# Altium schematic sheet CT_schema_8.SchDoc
size 391 x 238 mm
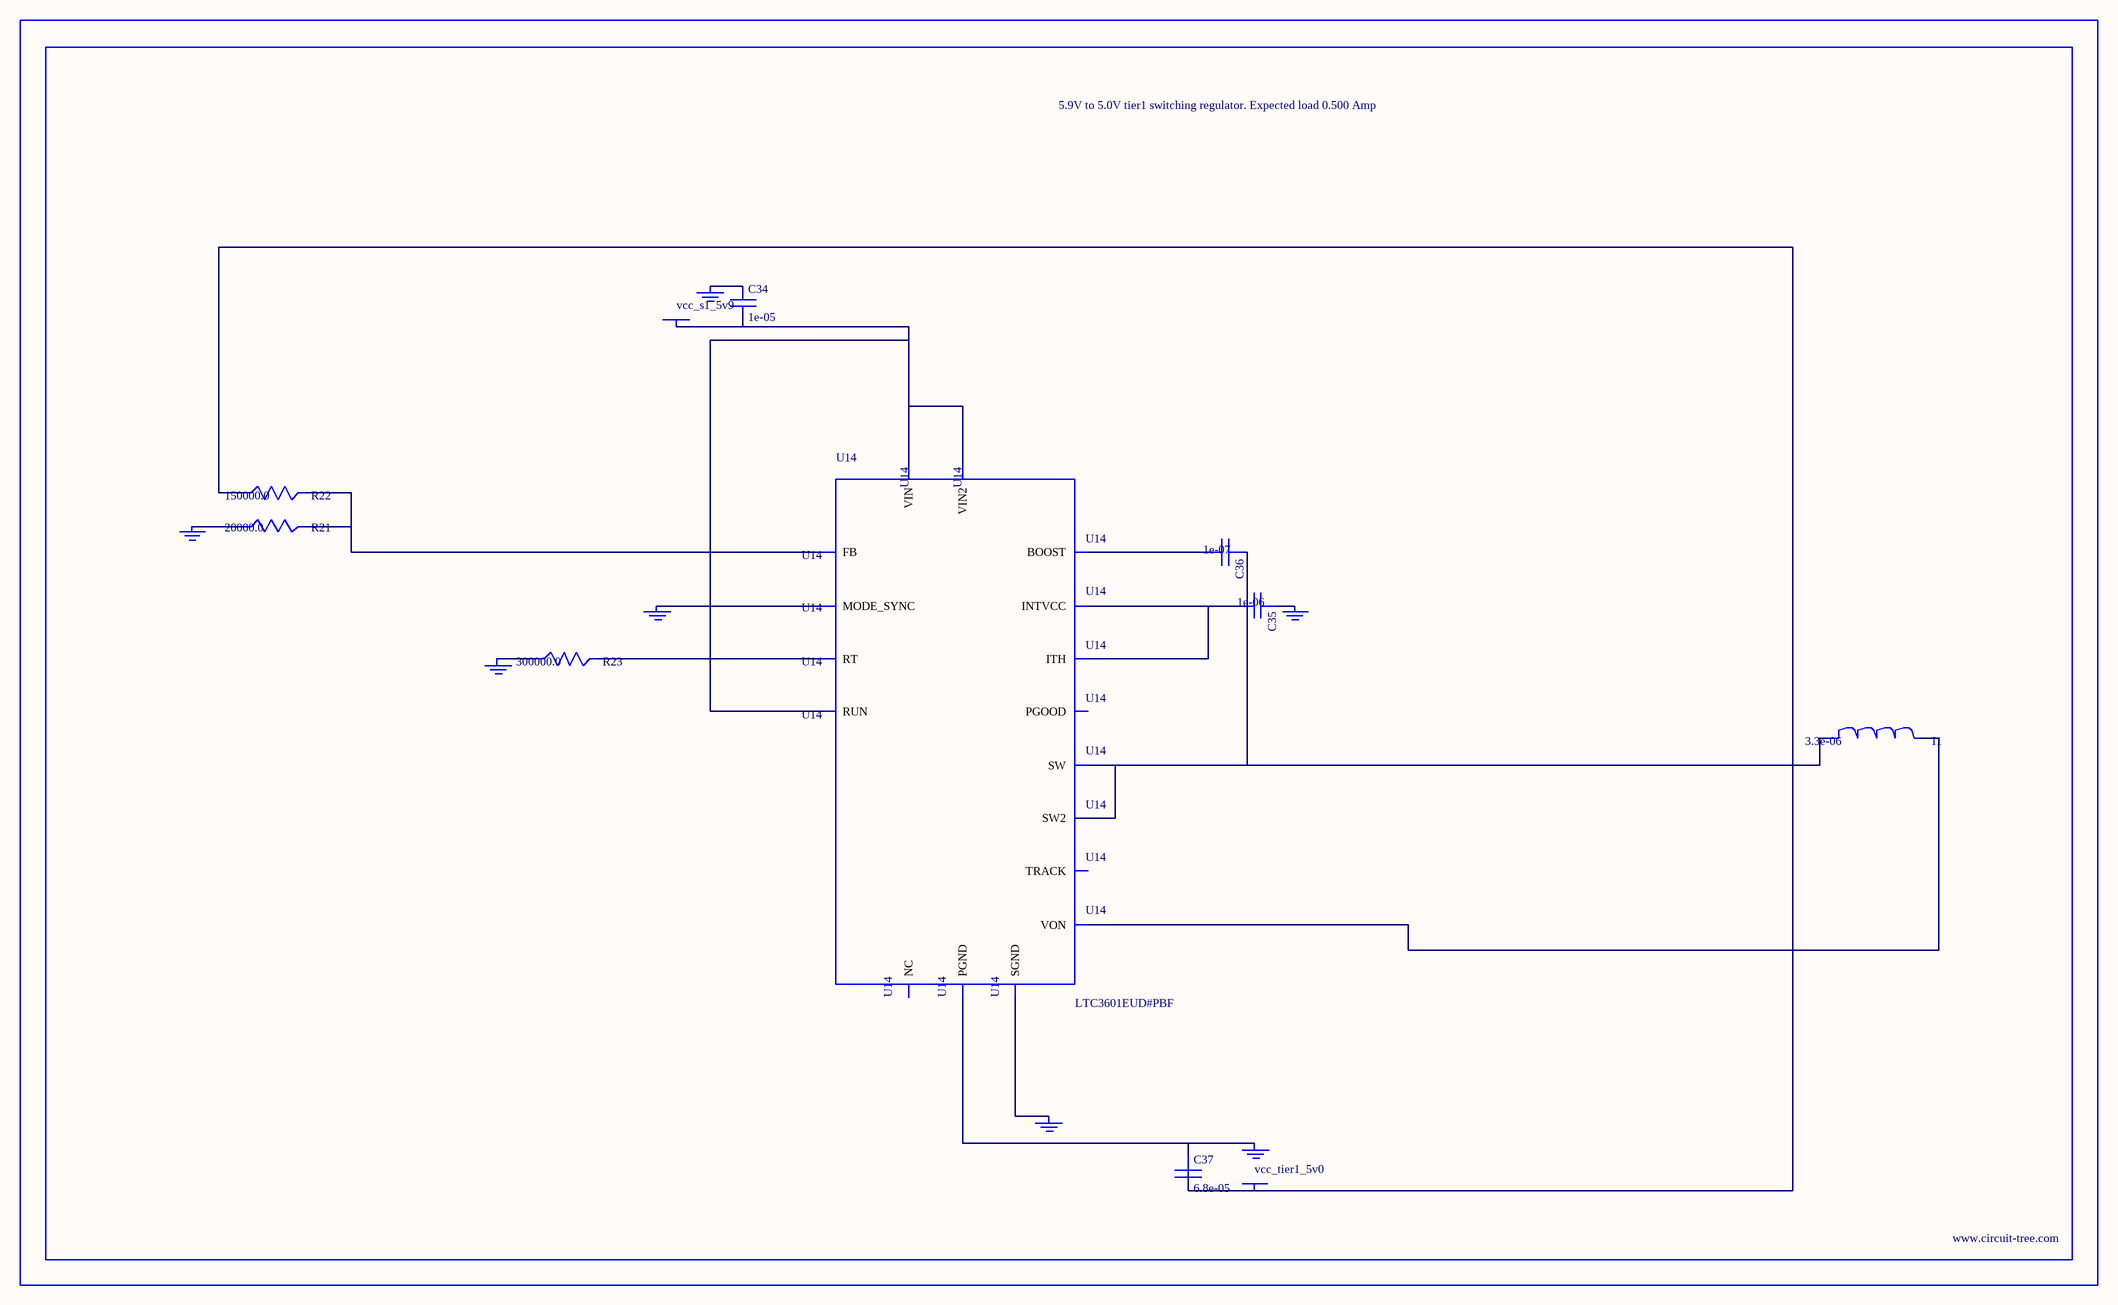
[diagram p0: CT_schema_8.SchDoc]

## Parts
BORDER7  (no value)
C34  1e-05  [C0805]
C35  1e-06  [C0603]
C36  1e-07  [C0402]
C37  6.8e-05  [2220]
GND_INSTANCE_7_0  (no value)
GND_INSTANCE_7_1  (no value)
GND_INSTANCE_7_2  (no value)
GND_INSTANCE_7_3  (no value)
GND_INSTANCE_7_4  (no value)
GND_INSTANCE_7_5  (no value)
GND_INSTANCE_7_6  (no value)
I1  3.3e-06  [WE-HCI_7030/7040/7050]
POWER_INSTANCE_7_0  vcc_s1_5v9
POWER_INSTANCE_7_1  vcc_tier1_5v0
R21  20000.0  [R0603]
R22  150000.0  [R0603]
R23  300000.0  [R0603]
U14  LTC3601EUD#PBF  [QFN-16_EP]

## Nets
NetC34_1: C34.1 GND_INSTANCE_7_5.0(GND)
NetC34_2: C34.2 POWER_INSTANCE_7_0.0(PWR) U14.14(RUN) U14.15(VIN) U14.16(VIN2)
NetC35_1: C35.1 GND_INSTANCE_7_1.0(GND)
NetC35_2: C35.2 U14.7(INTVCC) U14.12(ITH)
NetC36_1: C36.1 I1.1 U14.3(SW) U14.4(SW2)
NetC36_2: C36.2 U14.6(BOOST)
NetC37_1: C37.1 GND_INSTANCE_7_6.0(GND) U14.17(PGND)
NetC37_2: C37.2 I1.2 POWER_INSTANCE_7_1.0(PWR) R22.1 U14.8(VON)
NetGND_INSTANCE_7_0_0: GND_INSTANCE_7_0.0(GND) U14.1(MODE_SYNC)
NetGND_INSTANCE_7_2_0: GND_INSTANCE_7_2.0(GND) U14.9(SGND)
NetGND_INSTANCE_7_3_0: GND_INSTANCE_7_3.0(GND) R23.1
NetGND_INSTANCE_7_4_0: GND_INSTANCE_7_4.0(GND) R21.1
NetR21_2: R21.2 R22.2 U14.11(FB)
NetR23_2: R23.2 U14.10(RT)

Not connected (* = marked no-connect by the designer): U14 2(PGOOD) 5(NC) 13(TRACK)

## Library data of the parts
BORDER7 = BORDER_PAGE7
C34 = C0805C106K8RACTU
C35 = C0603C105K3RACTU
C36 = C0402C104K3RACTU
C37 = C5750X5R1A686M
GND_INSTANCE_7_0-GND_INSTANCE_7_6 = GND
I1 = 744314330
POWER_INSTANCE_7_0 POWER_INSTANCE_7_1 = PWR
R21 = RC0603JR-0720KL
R22 = RC0603JR-07150KL
R23 = RC0603JR-07300KL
